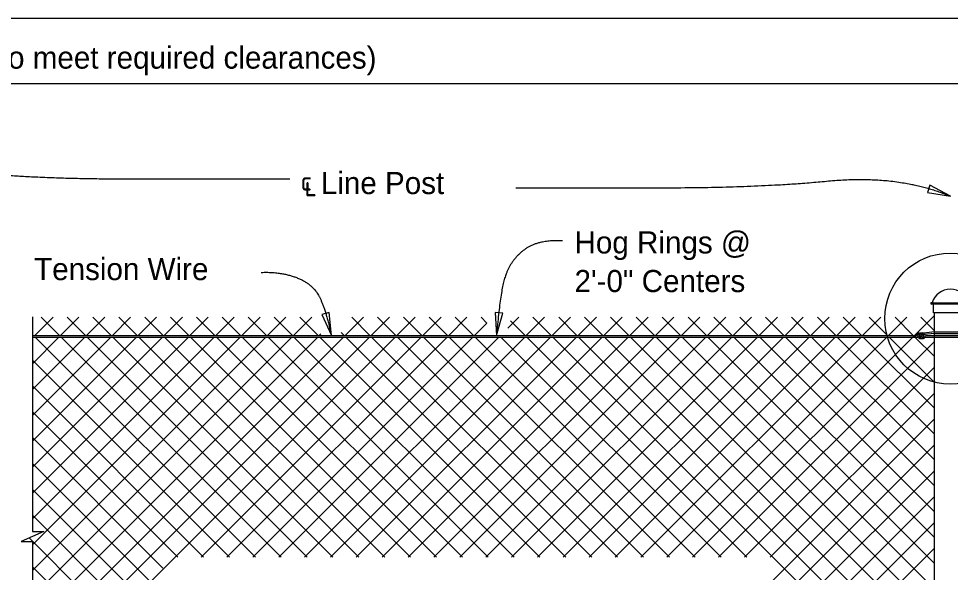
# Model space of a CAD drawing. Extents: x 0 to 72.1, y -15.2 to 30.1.
# Drawn here: x 16.14 to 24.63, y 22.95 to 28 of the extents above; entities that cross this region are included whole.
import ezdxf

# ---------------------------------------------------------------- set-up
doc = ezdxf.new("R2010")
doc.units = 0
for name, color, linetype in [('ActivePts-ConstElements', 7, 'Continuous'), ('Border', 7, 'Continuous'), ('Patterning', 7, 'Continuous'), ('PlotBorder_dp', 7, 'Continuous'), ('SheetLines_dp', 7, 'Continuous'), ('TextMisc', 7, 'Continuous')]:
    doc.layers.add(name, color=color, linetype=linetype)

msp = doc.modelspace()

# ---------------------------------------------------------------- linework, layer by layer
at = {"layer": 'ActivePts-ConstElements'}
msp.add_lwpolyline([(0.016, 2.0538), (41.0666, 2.0538), (41.0666, 27.9999), (0.016, 27.9999)], close=True, dxfattribs=at)
at = {"layer": 'Border'}
for p, q in [((24.4852, 25.1116), (24.7769, 25.1116)), ((24.4852, 25.0969), (24.7769, 25.0969))]:
    msp.add_line(p, q, dxfattribs=at)
at = {"layer": 'Patterning'}
for p, q in [((16.2896, 25.1116), (16.4562, 25.2783)), ((16.3488, 25.2783), (16.5155, 25.1116)), ((16.5253, 25.1116), (16.6919, 25.2783)), ((16.5845, 25.2783), (16.7512, 25.1116)), ((16.761, 25.1116), (16.9276, 25.2783)), ((16.8202, 25.2783), (16.9869, 25.1116)), ((16.9967, 25.1116), (17.1633, 25.2783)), ((17.0559, 25.2783), (17.2226, 25.1116)), ((17.2324, 25.1116), (17.3991, 25.2783)), ((17.2916, 25.2783), (17.4583, 25.1116)), ((17.4681, 25.1116), (17.6348, 25.2783)), ((17.5273, 25.2783), (17.694, 25.1116)), ((17.7038, 25.1116), (17.8705, 25.2783)), ((17.763, 25.2783), (17.9297, 25.1116)), ((17.9395, 25.1116), (18.1062, 25.2783)), ((17.9987, 25.2783), (18.1654, 25.1116)), ((18.1752, 25.1116), (18.3419, 25.2783)), ((18.2344, 25.2783), (18.4011, 25.1116)), ((18.4109, 25.1116), (18.5776, 25.2783)), ((18.4701, 25.2783), (18.6368, 25.1116)), ((18.6466, 25.1116), (18.8133, 25.2783)), ((18.7058, 25.2783), (18.8725, 25.1116)), ((19.118, 25.1116), (19.2847, 25.2783)), ((19.1772, 25.2783), (19.3439, 25.1116)), ((19.3537, 25.1116), (19.5204, 25.2783)), ((19.4129, 25.2783), (19.5796, 25.1116)), ((19.5894, 25.1116), (19.7561, 25.2783)), ((19.6486, 25.2783), (19.8153, 25.1116)), ((19.8251, 25.1116), (19.9918, 25.2783)), ((19.8843, 25.2783), (20.051, 25.1116)), ((20.0608, 25.1116), (20.2275, 25.2783)), ((20.12, 25.2783), (20.2867, 25.1116)), ((20.2965, 25.1116), (20.4095, 25.2246)), ((20.3557, 25.2783), (20.4095, 25.2246)), ((20.5989, 25.1783), (20.6989, 25.2783)), ((20.6246, 25.2452), (20.7581, 25.1116)), ((20.7679, 25.1116), (20.9346, 25.2783)), ((20.8271, 25.2783), (20.9938, 25.1116)), ((21.0036, 25.1116), (21.1703, 25.2783)), ((21.0628, 25.2783), (21.2295, 25.1116)), ((21.2393, 25.1116), (21.406, 25.2783)), ((21.2985, 25.2783), (21.4652, 25.1116)), ((21.475, 25.1116), (21.6417, 25.2783)), ((21.5342, 25.2783), (21.7009, 25.1116)), ((21.7107, 25.1116), (21.8774, 25.2783)), ((21.7699, 25.2783), (21.9366, 25.1116)), ((21.9464, 25.1116), (22.1131, 25.2783)), ((22.0057, 25.2783), (22.1723, 25.1116)), ((22.1821, 25.1116), (22.3488, 25.2783)), ((22.2414, 25.2783), (22.408, 25.1116)), ((22.2834, 23.0916), (24.4852, 25.2934)), ((22.4178, 25.1116), (22.5845, 25.2783)), ((22.4771, 25.2783), (22.6437, 25.1116)), ((22.6535, 25.1116), (22.8202, 25.2783)), ((22.7128, 25.2783), (22.8794, 25.1116)), ((22.8892, 25.1116), (23.0559, 25.2783)), ((22.9485, 25.2783), (23.1151, 25.1116)), ((23.1249, 25.1116), (23.2916, 25.2783)), ((23.1842, 25.2783), (23.3508, 25.1116)), ((23.3606, 25.1116), (23.5273, 25.2783)), ((23.4199, 25.2783), (23.5865, 25.1116)), ((23.5963, 25.1116), (23.763, 25.2783)), ((23.6556, 25.2783), (23.8222, 25.1116)), ((23.832, 25.1116), (23.9987, 25.2783)), ((23.8913, 25.2783), (24.0579, 25.1116)), ((24.0677, 25.1116), (24.2344, 25.2783)), ((24.127, 25.2783), (24.2936, 25.1116)), ((24.3035, 25.1116), (24.4701, 25.2783)), ((24.3627, 25.2783), (24.4852, 25.1557)), ((18.8823, 25.1116), (18.8973, 25.1266)), ((19.081, 25.1388), (19.1082, 25.1116)), ((16.268, 21.7902), (19.5747, 25.0969)), ((16.268, 22.2616), (19.1033, 25.0969)), ((16.268, 23.2044), (18.1604, 25.0969)), ((16.268, 22.733), (18.6318, 25.0969)), ((16.268, 22.0259), (19.339, 25.0969)), ((16.268, 22.4973), (18.8675, 25.0969)), ((16.268, 22.9687), (18.3961, 25.0969)), ((16.268, 23.4402), (17.9247, 25.0969)), ((16.268, 23.6759), (17.689, 25.0969)), ((16.268, 24.1473), (17.2176, 25.0969)), ((16.268, 23.9116), (17.4533, 25.0969)), ((16.268, 24.6187), (16.7462, 25.0969)), ((16.268, 25.0901), (16.2748, 25.0969)), ((16.268, 24.383), (16.9819, 25.0969)), ((16.268, 24.8544), (16.5105, 25.0969)), ((16.2945, 25.0969), (18.2998, 23.0916)), ((16.5302, 25.0969), (18.5355, 23.0916)), ((16.7659, 25.0969), (18.7712, 23.0916)), ((17.0016, 25.0969), (19.0069, 23.0916)), ((17.2373, 25.0969), (19.2426, 23.0916)), ((17.473, 25.0969), (19.4783, 23.0916)), ((17.7087, 25.0969), (19.714, 23.0916)), ((17.8051, 23.0916), (19.8104, 25.0969)), ((17.9444, 25.0969), (19.9497, 23.0916)), ((18.0408, 23.0916), (20.0461, 25.0969)), ((18.1801, 25.0969), (20.1854, 23.0916)), ((18.2765, 23.0916), (20.2818, 25.0969)), ((18.4158, 25.0969), (20.4211, 23.0916)), ((18.5122, 23.0916), (20.5175, 25.0969)), ((18.6515, 25.0969), (20.6568, 23.0916)), ((18.7479, 23.0916), (20.7532, 25.0969)), ((18.8872, 25.0969), (20.8925, 23.0916)), ((18.9836, 23.0916), (20.9889, 25.0969)), ((19.1229, 25.0969), (21.1282, 23.0916)), ((19.2193, 23.0916), (21.2246, 25.0969)), ((19.3586, 25.0969), (21.3639, 23.0916)), ((19.455, 23.0916), (21.4603, 25.0969)), ((19.5943, 25.0969), (21.5996, 23.0916)), ((19.6907, 23.0916), (21.696, 25.0969)), ((19.83, 25.0969), (21.8353, 23.0916)), ((19.9264, 23.0916), (21.9317, 25.0969)), ((20.0657, 25.0969), (22.071, 23.0916)), ((20.1621, 23.0916), (22.1674, 25.0969)), ((20.3015, 25.0969), (22.3067, 23.0916)), ((20.3978, 23.0916), (22.4031, 25.0969)), ((20.5372, 25.0969), (22.5424, 23.0916)), ((20.6335, 23.0916), (22.6388, 25.0969)), ((20.7729, 25.0969), (22.7781, 23.0916)), ((20.8692, 23.0916), (22.8745, 25.0969)), ((21.0086, 25.0969), (24.4852, 21.6202)), ((21.1049, 23.0916), (23.1102, 25.0969)), ((21.2443, 25.0969), (24.4852, 21.8559)), ((21.3406, 23.0916), (23.3459, 25.0969)), ((21.48, 25.0969), (24.4852, 22.0916)), ((21.5763, 23.0916), (23.5816, 25.0969)), ((21.7157, 25.0969), (24.4852, 22.3273)), ((21.812, 23.0916), (23.8173, 25.0969)), ((21.9514, 25.0969), (24.4852, 22.563)), ((22.0477, 23.0916), (24.053, 25.0969)), ((22.1871, 25.0969), (24.4852, 22.7987)), ((22.4228, 25.0969), (24.4852, 23.0344)), ((22.5191, 23.0916), (24.4852, 25.0577)), ((22.6585, 25.0969), (24.4852, 23.2701)), ((22.8942, 25.0969), (24.4852, 23.5058)), ((23.1299, 25.0969), (24.4852, 23.7415)), ((23.3656, 25.0969), (24.4852, 23.9772)), ((23.6013, 25.0969), (24.4852, 24.2129)), ((23.837, 25.0969), (24.4852, 24.4486)), ((24.0727, 25.0969), (24.4852, 24.6843)), ((24.3084, 25.0969), (24.4852, 24.92)), ((16.268, 24.8877), (18.0641, 23.0916)), ((22.7548, 23.0916), (24.4852, 24.822)), ((16.268, 24.652), (17.8284, 23.0916)), ((22.9905, 23.0916), (24.4852, 24.5863)), ((16.268, 24.4163), (17.5927, 23.0916)), ((23.0145, 22.8799), (24.4852, 24.3506)), ((16.268, 24.1806), (17.4577, 22.9909)), ((23.0145, 22.6442), (24.4852, 24.1149)), ((16.268, 23.9449), (17.4577, 22.7552)), ((23.0145, 22.4085), (24.4852, 23.8792)), ((16.268, 23.7092), (17.4577, 22.5195)), ((23.0145, 22.1728), (24.4852, 23.6435)), ((16.268, 23.4735), (17.4577, 22.2838)), ((21.9837, 20.9063), (24.4852, 23.4078)), ((16.2393, 23.2665), (17.4577, 22.0481)), ((22.2194, 20.9063), (24.4852, 23.1721)), ((16.268, 23.0021), (19.8104, 19.4597))]:
    msp.add_line(p, q, dxfattribs=at)
at = {"layer": 'PlotBorder_dp'}
for points in [[(13.631, 27.4094), (15.0947, 27.4094), (15.0947, 27.5128), (15.1397, 27.4094), (15.1847, 27.3061), (15.1847, 27.4094), (28.4756, 27.4094)], [(16.268, 25.2804), (16.268, 23.3241), (16.3714, 23.3241), (16.268, 23.2791), (16.1647, 23.2341), (16.268, 23.2341), (16.268, 22.3405)]]:
    msp.add_lwpolyline(points, dxfattribs=at)
for points in [[(24.6311, 26.3822), (24.4447, 26.4815), (24.4224, 26.4146)], [(18.9924, 25.1117), (18.9722, 25.3219), (18.9041, 25.3035)], [(20.4977, 25.1117), (20.5537, 25.3153), (20.4835, 25.3224)]]:
    msp.add_lwpolyline(points, close=True, dxfattribs=at)
msp.add_circle((24.631, 25.2659), 0.5976, dxfattribs=at)
for points in [[(18.6126, 26.5365), (17.8093, 26.5365), (16.42, 26.5365), (15.2385, 26.6311), (14.631, 26.7352)], [(20.6722, 26.4584), (21.1189, 26.4584), (22.8863, 26.4584), (24.1529, 26.5814), (24.631, 26.3821)], [(21.0973, 25.9736), (20.8794, 25.986), (20.6356, 25.8115), (20.5295, 25.5276), (20.4977, 25.1116)], [(18.354, 25.687), (18.5344, 25.6941), (18.8173, 25.5843), (18.9376, 25.3648), (18.9924, 25.1116)]]:
    msp.add_open_spline(points, degree=2, dxfattribs=at)
at = {"layer": 'TextMisc'}
for p, q in [((24.4587, 25.4103), (24.8033, 25.4103)), ((24.8033, 25.398), (24.4587, 25.398)), ((24.477, 25.3183), (24.477, 25.398)), ((24.7851, 25.3183), (24.477, 25.3183)), ((24.4852, 18.9432), (24.4852, 25.3183)), ((24.4852, 25.1443), (24.3904, 25.1332)), ((24.4852, 25.1297), (24.3926, 25.1202)), ((24.4852, 25.1443), (24.7764, 25.1459)), ((24.4852, 25.1297), (24.7764, 25.1314)), ((16.268, 25.1116), (24.3101, 25.1116)), ((16.268, 25.0969), (24.3367, 25.0969)), ((24.32, 25.1116), (24.3332, 25.1116)), ((24.4016, 25.0969), (24.4852, 25.0969)), ((24.4031, 25.1116), (24.4852, 25.1116))]:
    msp.add_line(p, q, dxfattribs=at)
msp.add_arc((24.4589, 25.404), 0.00613, 91.1647, 268.8353, dxfattribs=at)
for centre, major_axis, ratio, start_param, end_param in [((24.6317, 25.3692), (0.1711, 0), 0.957868, 0.252602, 2.888574), ((24.3443, 25.0974), (0.0373, 0), 0.957868, 1.486836, 3.108042), ((24.3568, 25.1119), (0.023, 0), 0.957868, 1.29026, 2.970541), ((24.3756, 25.1065), (0.0295, 0), 0.957868, 1.220941, 4.039556), ((24.389, 25.1083), (-0.0303, -0.0108), 0.724765, 4.35367, 6.324556), ((24.3654, 25.0577), (-0.0724, 0), 0.957868, 5.162149, 5.652106), ((24.358, 25.1093), (-0.0249, 0), 0.957868, 6.009018, 7.089857), ((24.3593, 25.1053), (0.0231, 0), 0.957868, 3.779554, 4.879821), ((24.3654, 25.0997), (0.0206, -0.0021), 0.798607, 4.32653, 5.220153), ((24.3789, 25.0997), (0.0206, -0.0021), 0.798607, 3.333154, 5.220153), ((24.3857, 25.1042), (-0.0139, 0), 0.957868, 5.22362, 6.905413), ((24.3801, 25.1018), (-0.00795, 0), 0.957868, 6.140374, 9.314262), ((24.3941, 25.0953), (-0.0259, 0), 0.957868, 4.777514, 5.62749), ((24.3784, 25.1076), (0.0119, 0), 0.957868, 5.725876, 7.416677), ((24.3715, 25.1184), (0.0391, 0), 0.957868, 5.082588, 5.41974), ((24.3784, 25.1076), (0.0119, 0), 0.957868, 5.639684, 5.723117), ((24.3786, 25.1064), (0.0251, 0), 0.957868, 5.531357, 6.227833), ((24.3786, 25.1064), (0.0251, 0), 0.957868, 0.407687, 0.609214)]:
    msp.add_ellipse(centre, major_axis=major_axis, ratio=ratio, start_param=start_param, end_param=end_param, dxfattribs=at)

# ---------------------------------------------------------------- texts
at = {"layer": 'PlotBorder_dp'}
for s, p in [('Hog Rings @ ', (21.2071, 25.8593)), ('2\'-0" Centers', (21.2071, 25.5073))]:
    msp.add_text(s, height=0.2016, dxfattribs=at).set_placement(p)
at = {"layer": 'SheetLines_dp'}
for s, p in [('Equal Spaces @ 10\'-0" Max. (Posts may be shifted minimally to meet required clearances)', (8.5986, 27.544)), ('℄ Line Post', (18.7118, 26.4008)), ('Tension Wire', (16.284, 25.6165))]:
    msp.add_text(s, height=0.2016, dxfattribs=at).set_placement(p)

doc.saveas('drawing.dxf')
